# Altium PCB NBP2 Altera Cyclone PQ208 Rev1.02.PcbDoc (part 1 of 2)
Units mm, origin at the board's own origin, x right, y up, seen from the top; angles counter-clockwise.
Board outline 69 x 80.99 mm, 2 copper layers (Top Layer, Bottom Layer); 52 components, 189 nets, 558 pads, 192 vias.
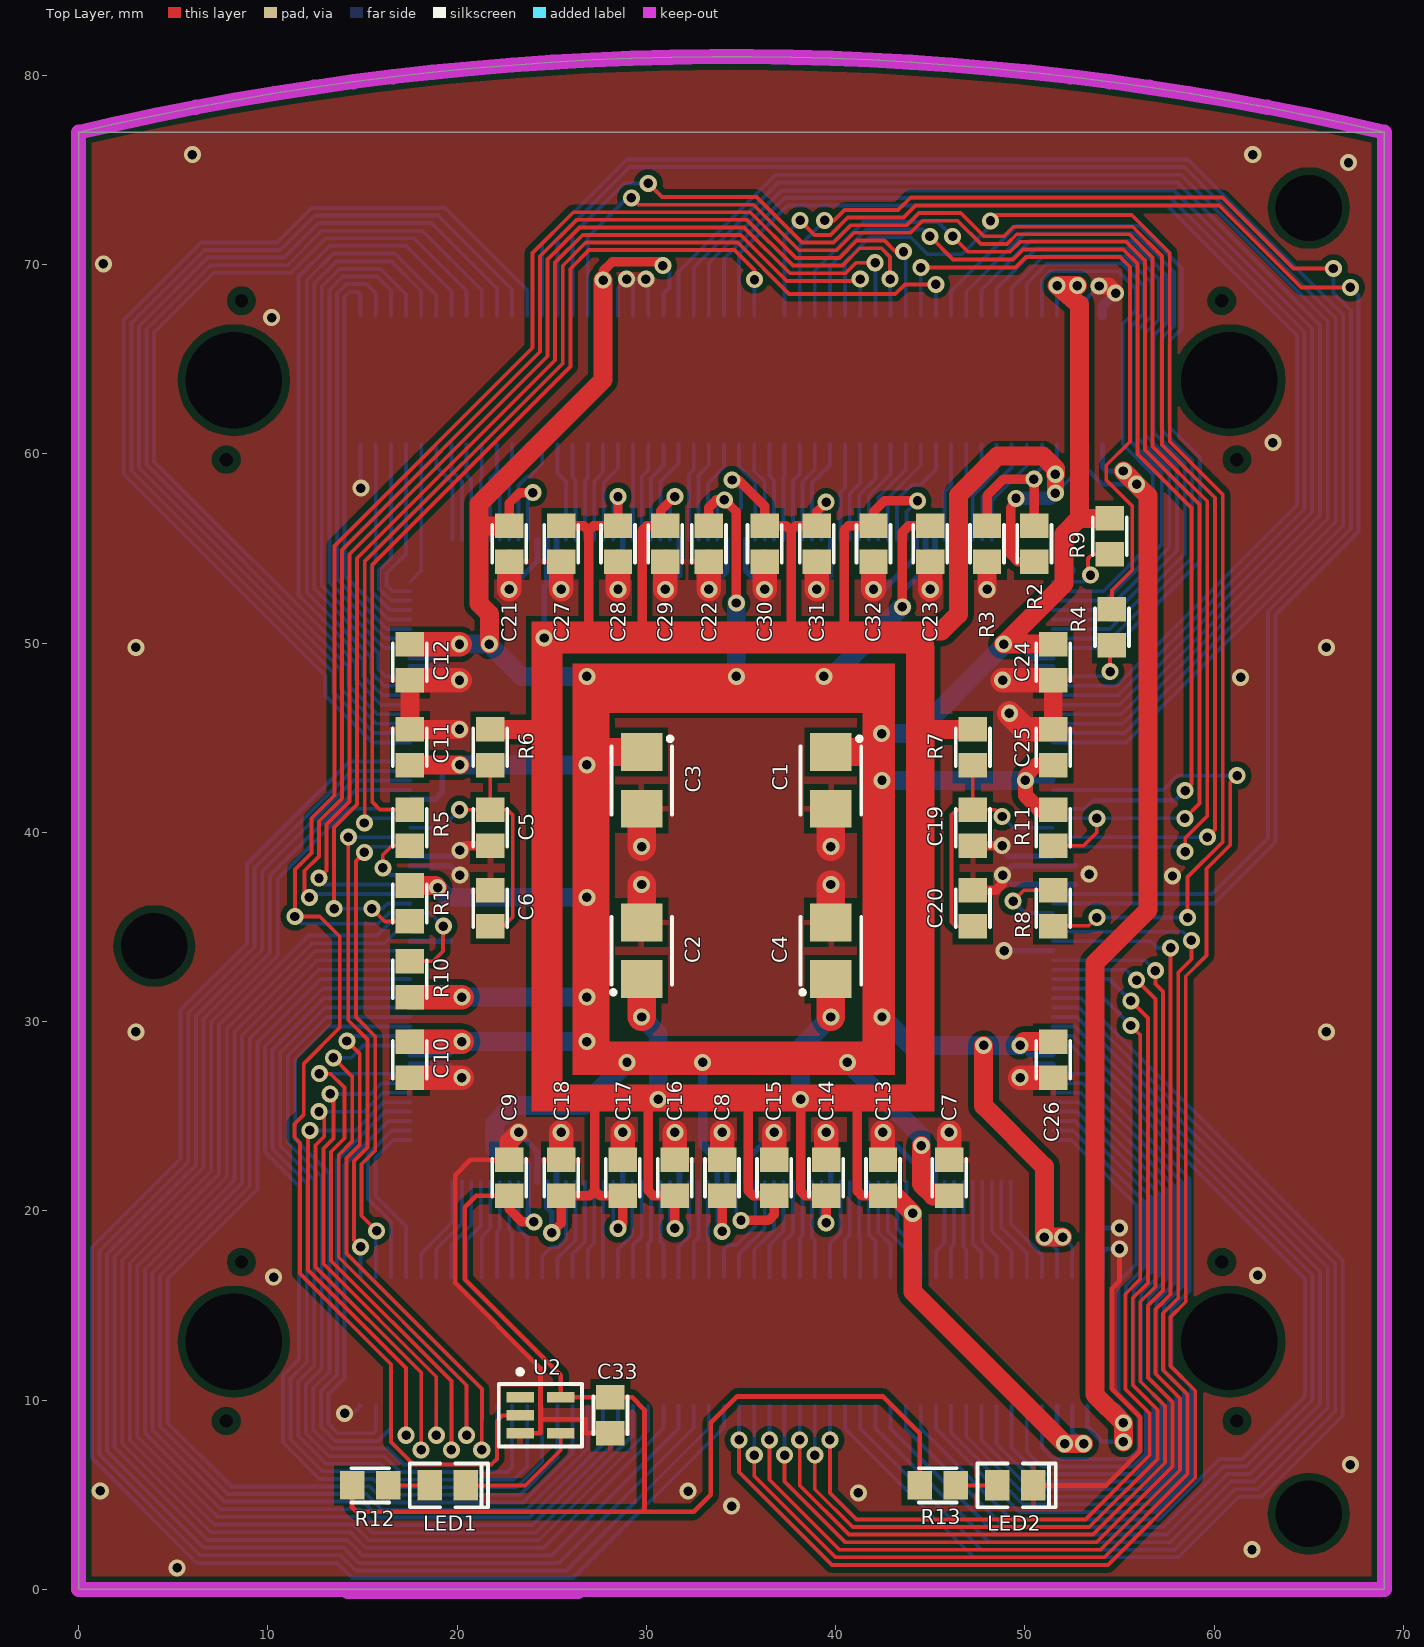
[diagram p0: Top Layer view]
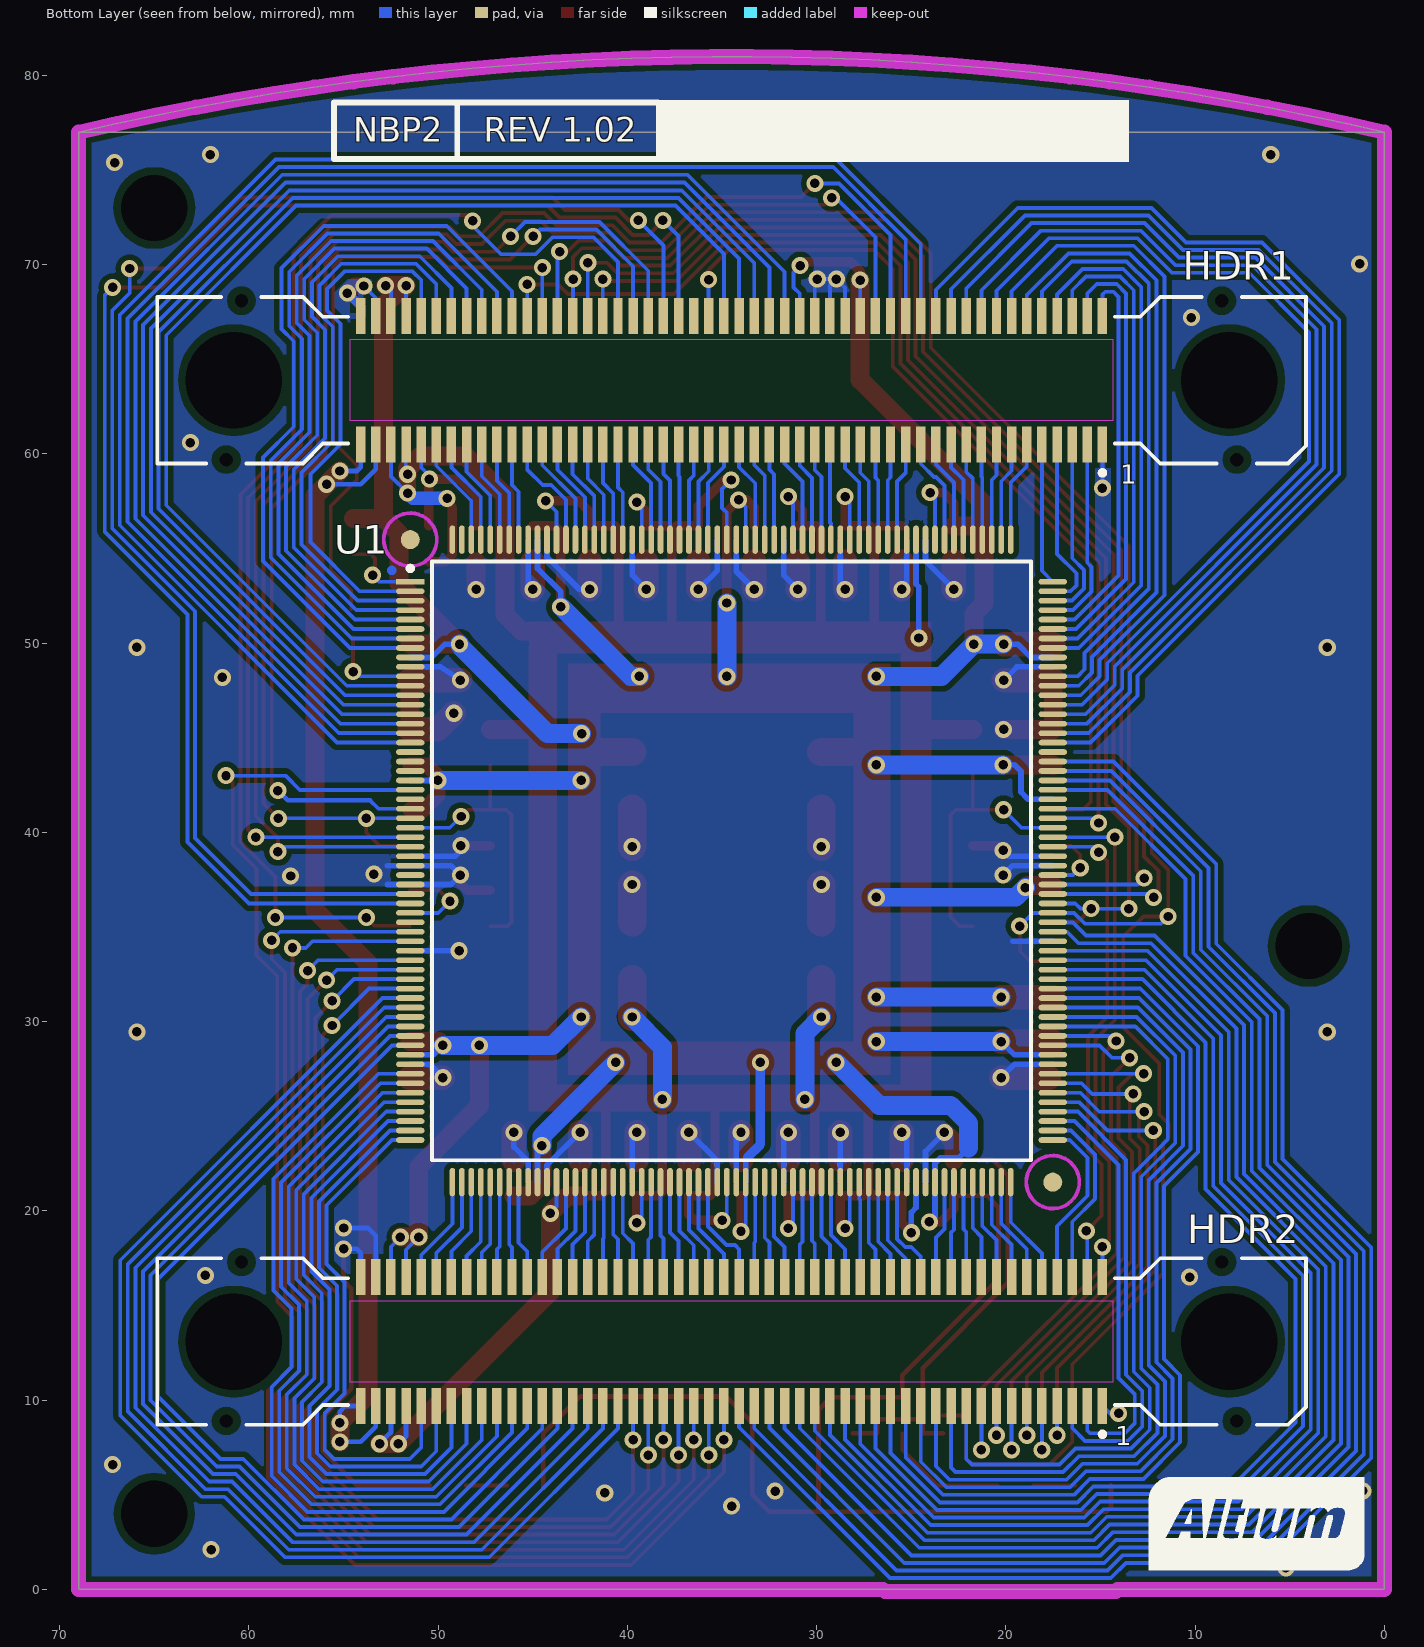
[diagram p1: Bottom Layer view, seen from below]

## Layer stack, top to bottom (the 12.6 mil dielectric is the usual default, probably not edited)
Top Layer: signal copper 0.0356
Dielectric: core 0.32, FR-4, Dk 4.8
Bottom Layer: signal copper 0.0356

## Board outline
0,0 0,77 ccw(c0.001,77) 0.001,77 cw(c34.5,-69.801) 0.001,77 69,77 69,0

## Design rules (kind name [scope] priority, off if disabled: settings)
Clearance Clearance_Unplated_Pads [PadIsPlated = 'False'] p1: gap=0.4 // Slightly larger clearance around unplated holes
Clearance Clearance_Polygons [InPolygon] p2: gap=0.3
Clearance [All] p3: gap=0.2
ComponentClearance [All] p1: gap=0.2 collisioncheckmode=3 verticalgap=0.254 showdistances=FALSE
FabricationTestPointUsage TestPointUsage [All] p1 off: valid=0 allowmultiple=FALSE
FabricationTestpoint Testpoint [All] p1 off: side=3 testpointundercomponent=TRUE minsize=1.016 maxsize=2.54 preferedsize=1.524 minholesize=0 maxholesize=1.016 preferedholesize=0.813 testpointgrid=0.025 allowsidetop=TRUE allowsidebottom=TRUE usegrid=TRUE gridtolerance=0
HoleSize [All] p1: absolutevalues=TRUE maxlimit=5.2 minlimit=0.4 maxpercent=80.000 minpercent=20.000
PlaneClearance [All] p1: clearance=0.5
PlaneConnect [All] p1: planeconnectstyle=Relief reliefexpansion=0.5 reliefentries=4 reliefconductorwidth=0.25 reliefairgap=0.25
PolygonConnect PolygonConnect_Satellite_ID_Pads [InPadClass('Satellite ID Pads')] p1: connectstyle=NoConnect reliefconductorwidth=0.254 reliefentries=4 polygonreliefangle="90 Angle"
PolygonConnect [All] p2: connectstyle=Relief reliefconductorwidth=0.3 reliefentries=4 polygonreliefangle="90 Angle"
RoomDefinition BOCD_CycloneEPC12 [InComponentClass('BOCD_CycloneEPC12')] p1 off: confinementstyle=ConfineIn formatcopy=TRUE lockcomponents=FALSE outline 0,0 69,0 69,77 0,77
RoutingVias [All] p1: holewidth=0.5 width=0.9 viastyle="Through Hole" minholewidth=0.5 minwidth=0.9 maxholewidth=0.5 maxwidth=0.9
SMDNeckDown [All] p1: percent=100.000
SilkscreenOverComponentPads [All] p1: minsilkscreentomaskgap=0.254
SolderMaskExpansion SolderMaskExpansion_Vias [Isvia] p1: expansion=-0.46
SolderMaskExpansion [All] p2: expansion=0.1
Width Width_Power_Nets [InNetClass('Power Nets')] p1: maxlimit=2.5 minlimit=0.15 preferedwidth=0.25 toplayer_prefwidth=0.15
Width [All] p2: maxlimit=1.5 minlimit=0.2 preferedwidth=0.2
21 further rules are at their usual default settings.

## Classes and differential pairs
pad class "Satellite ID Pads": HDR1-36 HDR1-38 HDR1-40
net class "Power Nets": 5V GND VCC VCCINT

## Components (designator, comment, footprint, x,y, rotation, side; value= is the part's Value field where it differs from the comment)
C1 "10uF" MCCT-B 39.75,42.75 r270 top
C2 "10uF" MCCT-B 29.75,33.75 r90 top
C3 "10uF" MCCT-B 29.75,42.75 r270 top
C4 "10uF" MCCT-B 39.75,33.75 r90 top
C5 "0.1uF" CC2012-0805 21.75,40.25 r270 top
C6 "0.001uF" CC2012-0805 21.75,36 r90 top
C7 "0.1uF" CC2012-0805 46,21.75 r90 top
C8 "0.1uF" CC2012-0805 34,21.75 r90 top
C9 "0.1uF" CC2012-0805 22.75,21.75 r90 top
C10 "0.1uF" CC2012-0805 17.5,28 r270 top
C11 "0.1uF" CC2012-0805 17.5,44.5 r90 top
C12 "0.1uF" CC2012-0805 17.5,49 r270 top
C13 "0.1uF" CC2012-0805 42.5,21.75 r90 top
C14 "0.1uF" CC2012-0805 39.5,21.75 r90 top
C15 "0.1uF" CC2012-0805 36.75,21.75 r90 top
C16 "0.1uF" CC2012-0805 31.5,21.75 r90 top
C17 "0.1uF" CC2012-0805 28.75,21.75 r90 top
C18 "0.1uF" CC2012-0805 25.5,21.75 r90 top
C19 "0.1uF" CC2012-0805 47.25,40.25 r90 top
C20 "0.001uF" CC2012-0805 47.25,36 r270 top
C21 "0.1uF" CC2012-0805 22.75,55.25 r90 top
C22 "0.1uF" CC2012-0805 33.3,55.25 r90 top
C23 "0.1uF" CC2012-0805 45,55.25 r90 top
C24 "0.1uF" CC2012-0805 51.5,49 r90 top
C25 "0.1uF" CC2012-0805 51.5,44.5 r270 top
C26 "0.1uF" CC2012-0805 51.5,28 r90 top
C27 "0.1uF" CC2012-0805 25.5,55.25 r90 top
C28 "0.1uF" CC2012-0805 28.5,55.25 r90 top
C29 "0.1uF" CC2012-0805 31,55.25 r90 top
C30 "0.1uF" CC2012-0805 36.25,55.25 r90 top
C31 "0.1uF" CC2012-0805 39,55.25 r90 top
C32 "0.1uF" CC2012-0805 42,55.25 r90 top
C33 "0.1uF" CC2012-0805 28.1,9.2 r270 top
HDR1 "54075-1009" 54075 34.5,63.9 r0 bottom locked
HDR2 "54075-1009" 54075 34.5,13.1 r0 bottom locked
LED1 "HSMG-C170" "SMD _LED" 19.5,5.5 r180 top locked
LED2 "HSMH-C170" "SMD _LED" 49.5,5.5 r180 top locked
R1 "4K7" CC2012-0805 17.5,36.25 r270 top
R2 "DO NOT INSTALL" CC2012-0805 50.5,55.25 r90 top
R3 "47R" CC2012-0805 48,55.25 r270 top
R4 "100R" CC2012-0805 54.6,50.85 r90 top
R5 "100R" CC2012-0805 17.5,40.25 r270 top
R6 "1R" CC2012-0805 21.75,44.5 r270 top
R7 "1R" CC2012-0805 47.25,44.5 r270 top
R8 "33R" CC2012-0805 51.5,36 r270 top
R9 "4K7" CC2012-0805 54.483,55.651 r270 top
R10 "4K7" CC2012-0805 17.5,32.25 r90 top
R11 "4K7" CC2012-0805 51.5,40.25 r270 top
R12 "270R" CC2012-0805 15.4,5.5 r0 top
R13 "270R" CC2012-0805 45.4,5.5 r0 top
U1 "Cyclone EP1C12Q240C8" F-QFP32X32-G240/P.5N(RS) 34.5,38.5 r180 bottom locked
U2 "SN74LVC1G04DBV" SO-G5/P.95 24.4,9.2 r270 top

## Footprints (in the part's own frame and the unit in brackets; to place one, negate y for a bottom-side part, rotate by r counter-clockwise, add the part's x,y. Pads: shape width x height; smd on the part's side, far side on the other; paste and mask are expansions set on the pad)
54075 [mm] "Connector; Docking Station, Receptacle; 100 Position; Vertical"
  rect 0.5x1.9 smd: 1(-19.6,3.4) 2(-19.6,-3.4) 3(-18.8,3.4) 4(-18.8,-3.4) 5(-18,3.4) 6(-18,-3.4) 7(-17.2,3.4) 8(-17.2,-3.4) 9(-16.4,3.4) 10(-16.4,-3.4) 11(-15.6,3.4) 12(-15.6,-3.4) 13(-14.8,3.4) 14(-14.8,-3.4) 15(-14,3.4) 16(-14,-3.4) 17(-13.2,3.4) 18(-13.2,-3.4) 19(-12.4,3.4) 20(-12.4,-3.4) 21(-11.6,3.4) 22(-11.6,-3.4) 23(-10.8,3.4) 24(-10.8,-3.4) 25(-10,3.4) 26(-10,-3.4) 27(-9.2,3.4) 28(-9.2,-3.4) 29(-8.4,3.4) 30(-8.4,-3.4) 31(-7.6,3.4) 32(-7.6,-3.4) 33(-6.8,3.4) 34(-6.8,-3.4) 35(-6,3.4) 36(-6,-3.4) 37(-5.2,3.4) 38(-5.2,-3.4) 39(-4.4,3.4) 40(-4.4,-3.4) 41(-3.6,3.4) 42(-3.6,-3.4) 43(-2.8,3.4) 44(-2.8,-3.4) 45(-2,3.4) 46(-2,-3.4) 47(-1.2,3.4) 48(-1.2,-3.4) 49(-0.4,3.4) 50(-0.4,-3.4) 51(0.4,3.4) 52(0.4,-3.4) 53(1.2,3.4) 54(1.2,-3.4) 55(2,3.4) 56(2,-3.4) 57(2.8,3.4) 58(2.8,-3.4) 59(3.6,3.4) 60(3.6,-3.4) 61(4.4,3.4) 62(4.4,-3.4) 63(5.2,3.4) 64(5.2,-3.4) 65(6,3.4) 66(6,-3.4) 67(6.8,3.4) 68(6.8,-3.4) 69(7.6,3.4) 70(7.6,-3.4) 71(8.4,3.4) 72(8.4,-3.4) 73(9.2,3.4) 74(9.2,-3.4) 75(10,3.4) 76(10,-3.4) 77(10.8,3.4) 78(10.8,-3.4) 79(11.6,3.4) 80(11.6,-3.4) 81(12.4,3.4) 82(12.4,-3.4) 83(13.2,3.4) 84(13.2,-3.4) 85(14,3.4) 86(14,-3.4) 87(14.8,3.4) 88(14.8,-3.4) 89(15.6,3.4) 90(15.6,-3.4) 91(16.4,3.4) 92(16.4,-3.4) 93(17.2,3.4) 94(17.2,-3.4) 95(18,3.4) 96(18,-3.4) 97(18.8,3.4) 98(18.8,-3.4) 99(19.6,3.4) 100(19.6,-3.4)
  round 0.5 hole 0.7 unplated: MH1(-26.7,4.2) MH2(-25.9,-4.2) MH3(26.7,4.2) MH4(25.9,-4.2)
  round 4.8 hole 5.1 unplated: MH5(-26.3,0) MH6(26.3,0)
  Top Layer keep-out region: -20.15,2.15 20.15,2.15 20.15,-2.15 -20.15,-2.15
  silkscreen extent -30.35,-4.4 30.35,5.02
CC2012-0805 [mm]
  rect 1.3x1.5 smd: 1(-0.95,0) 2(0.95,0)
  silkscreen extent -1,-0.9 1,0.9
F-QFP32X32-G240/P.5N(RS) [mm]
  rect 1.5x0.3 smd: 1(-16.975,14.75)
  oval 1.5x0.3 smd: 2(-16.975,14.25) 3(-16.975,13.75) 4(-16.975,13.25) 5(-16.975,12.75) 6(-16.975,12.25) 7(-16.975,11.75) 8(-16.975,11.25) 9(-16.975,10.75) 10(-16.975,10.25) 11(-16.975,9.75) 12(-16.975,9.25) 13(-16.975,8.75) 14(-16.975,8.25) 15(-16.975,7.75) 16(-16.975,7.25) 17(-16.975,6.75) 18(-16.975,6.25) 19(-16.975,5.75) 20(-16.975,5.25) 21(-16.975,4.75) 22(-16.975,4.25) 23(-16.975,3.75) 24(-16.975,3.25) 25(-16.975,2.75) 26(-16.975,2.25) 27(-16.975,1.75) 28(-16.975,1.25) 29(-16.975,0.75) 30(-16.975,0.25) 31(-16.975,-0.25) 32(-16.975,-0.75) 33(-16.975,-1.25) 34(-16.975,-1.75) 35(-16.975,-2.25) 36(-16.975,-2.75) 37(-16.975,-3.25) 38(-16.975,-3.75) 39(-16.975,-4.25) 40(-16.975,-4.75) 41(-16.975,-5.25) 42(-16.975,-5.75) 43(-16.975,-6.25) 44(-16.975,-6.75) 45(-16.975,-7.25) 46(-16.975,-7.75) 47(-16.975,-8.25) 48(-16.975,-8.75) 49(-16.975,-9.25) 50(-16.975,-9.75) 51(-16.975,-10.25) 52(-16.975,-10.75) 53(-16.975,-11.25) 54(-16.975,-11.75) 55(-16.975,-12.25) 56(-16.975,-12.75) 57(-16.975,-13.25) 58(-16.975,-13.75) 59(-16.975,-14.25) 60(-16.975,-14.75) 121(16.975,-14.75) 122(16.975,-14.25) 123(16.975,-13.75) 124(16.975,-13.25) 125(16.975,-12.75) 126(16.975,-12.25) 127(16.975,-11.75) 128(16.975,-11.25) 129(16.975,-10.75) 130(16.975,-10.25) 131(16.975,-9.75) 132(16.975,-9.25) 133(16.975,-8.75) 134(16.975,-8.25) 135(16.975,-7.75) 136(16.975,-7.25) 137(16.975,-6.75) 138(16.975,-6.25) 139(16.975,-5.75) 140(16.975,-5.25) 141(16.975,-4.75) 142(16.975,-4.25) 143(16.975,-3.75) 144(16.975,-3.25) 145(16.975,-2.75) 146(16.975,-2.25) 147(16.975,-1.75) 148(16.975,-1.25) 149(16.975,-0.75) 150(16.975,-0.25) 151(16.975,0.25) 152(16.975,0.75) 153(16.975,1.25) 154(16.975,1.75) 155(16.975,2.25) 156(16.975,2.75) 157(16.975,3.25) 158(16.975,3.75) 159(16.975,4.25) 160(16.975,4.75) 161(16.975,5.25) 162(16.975,5.75) 163(16.975,6.25) 164(16.975,6.75) 165(16.975,7.25) 166(16.975,7.75) 167(16.975,8.25) 168(16.975,8.75) 169(16.975,9.25) 170(16.975,9.75) 171(16.975,10.25) 172(16.975,10.75) 173(16.975,11.25) 174(16.975,11.75) 175(16.975,12.25) 176(16.975,12.75) 177(16.975,13.25) 178(16.975,13.75) 179(16.975,14.25) 180(16.975,14.75)
  oval 0.3x1.5 smd: 61(-14.75,-16.975) 62(-14.25,-16.975) 63(-13.75,-16.975) 64(-13.25,-16.975) 65(-12.75,-16.975) 66(-12.25,-16.975) 67(-11.75,-16.975) 68(-11.25,-16.975) 69(-10.75,-16.975) 70(-10.25,-16.975) 71(-9.75,-16.975) 72(-9.25,-16.975) 73(-8.75,-16.975) 74(-8.25,-16.975) 75(-7.75,-16.975) 76(-7.25,-16.975) 77(-6.75,-16.975) 78(-6.25,-16.975) 79(-5.75,-16.975) 80(-5.25,-16.975) 81(-4.75,-16.975) 82(-4.25,-16.975) 83(-3.75,-16.975) 84(-3.25,-16.975) 85(-2.75,-16.975) 86(-2.25,-16.975) 87(-1.75,-16.975) 88(-1.25,-16.975) 89(-0.75,-16.975) 90(-0.25,-16.975) 91(0.25,-16.975) 92(0.75,-16.975) 93(1.25,-16.975) 94(1.75,-16.975) 95(2.25,-16.975) 96(2.75,-16.975) 97(3.25,-16.975) 98(3.75,-16.975) 99(4.25,-16.975) 100(4.75,-16.975) 101(5.25,-16.975) 102(5.75,-16.975) 103(6.25,-16.975) 104(6.75,-16.975) 105(7.25,-16.975) 106(7.75,-16.975) 107(8.25,-16.975) 108(8.75,-16.975) 109(9.25,-16.975) 110(9.75,-16.975) 111(10.25,-16.975) 112(10.75,-16.975) 113(11.25,-16.975) 114(11.75,-16.975) 115(12.25,-16.975) 116(12.75,-16.975) 117(13.25,-16.975) 118(13.75,-16.975) 119(14.25,-16.975) 120(14.75,-16.975) 181(14.75,16.975) 182(14.25,16.975) 183(13.75,16.975) 184(13.25,16.975) 185(12.75,16.975) 186(12.25,16.975) 187(11.75,16.975) 188(11.25,16.975) 189(10.75,16.975) 190(10.25,16.975) 191(9.75,16.975) 192(9.25,16.975) 193(8.75,16.975) 194(8.25,16.975) 195(7.75,16.975) 196(7.25,16.975) 197(6.75,16.975) 198(6.25,16.975) 199(5.75,16.975) 200(5.25,16.975) 201(4.75,16.975) 202(4.25,16.975) 203(3.75,16.975) 204(3.25,16.975) 205(2.75,16.975) 206(2.25,16.975) 207(1.75,16.975) 208(1.25,16.975) 209(0.75,16.975) 210(0.25,16.975) 211(-0.25,16.975) 212(-0.75,16.975) 213(-1.25,16.975) 214(-1.75,16.975) 215(-2.25,16.975) 216(-2.75,16.975) 217(-3.25,16.975) 218(-3.75,16.975) 219(-4.25,16.975) 220(-4.75,16.975) 221(-5.25,16.975) 222(-5.75,16.975) 223(-6.25,16.975) 224(-6.75,16.975) 225(-7.25,16.975) 226(-7.75,16.975) 227(-8.25,16.975) 228(-8.75,16.975) 229(-9.25,16.975) 230(-9.75,16.975) 231(-10.25,16.975) 232(-10.75,16.975) 233(-11.25,16.975) 234(-11.75,16.975) 235(-12.25,16.975) 236(-12.75,16.975) 237(-13.25,16.975) 238(-13.75,16.975) 239(-14.25,16.975) 240(-14.75,16.975)
  round 1 smd paste-0.51 mask+1: FID1(-16.975,16.975) FID2(16.975,-16.975)
  Top Layer circle w0.25: c-17.951,15.348 r0.125
  Top Layer keep-out circle w0.2: c-16.975,16.975 r1.4
  Top Layer keep-out circle w0.2: c16.975,-16.975 r1.4
  silkscreen extent -17.1,-15.83 15.83,15.83
MCCT-B [mm]
  rect 2x2.2 smd: 1(-1.5,0) 2(1.5,0)
  silkscreen extent -2.3,-1.6 1.8,1.6
"SMD _LED" [mm]
  rect 1.3x1.6 smd: 1(0.95,0) 2(-0.95,0)
  silkscreen extent -2.13,-1.15 2,1.15
SO-G5/P.95 [mm]
  rect 0.55x1.45 smd: 1(-0.95,-1.075) 2(0,-1.075) 3(0.95,-1.075) 4(0.95,1.075) 5(-0.95,1.075)
  silkscreen extent -2.42,-2.2 1.65,2.2

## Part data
C1 C2 C3 C4: library part CAP_POLAR, "Polar Capacitor"
C5 C6 C7 C8 C9 C10 C11 C12 C13 C14 C15 C16 C17 C18 C19 C20 C21 C22 C23 C24 C25 C26 C27 C28 C29 C30 C31 C32 C33: library part CAP, "Capacitor"
HDR1 HDR2: "Board-to-Board, Docking Station, 0.80mm (.031\") Pitch, Shielded Receptacle, Vertical, Ultra Low Profile, SMT"
LED1 LED2: library part HSMX-C670, "Typical RED GaAs SMD LED Agilent make"
R1 R2 R3 R4 R5 R6 R7 R8 R9 R10 R11 R12 R13: library part RES, "Resistor"
U1: library part EP1C12Q240C6_ALT, "Cyclone Family, 1.5V FPGA, 173 I/O Pins, 2 x PLLs, Commercial Grade, Speed Grade 6"
U2: library part SN74AHC1G04DBVR

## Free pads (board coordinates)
  round 3.2 hole 3.5 unplated: LP(4,34) LP(65,4) LP(65,73)

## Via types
v1: diameter 0.9, hole 0.5, Top Layer to Bottom Layer, 192 vias

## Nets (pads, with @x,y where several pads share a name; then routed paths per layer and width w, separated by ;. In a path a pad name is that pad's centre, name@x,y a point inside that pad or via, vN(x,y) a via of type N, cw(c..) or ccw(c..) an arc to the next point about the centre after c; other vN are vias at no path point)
5V: HDR1.97 HDR1.99 HDR2.97 HDR2.99 | length 65.4
  Top Layer w1: v1(55.2,7.8) v1(55.2,8.8) 53.7,10.3 53.7,33.1 56.5,35.9 56.5,57.8 v1(55.2,59.1)
  Bottom Layer w0.25: HDR2.97@53.3,9.7 53.3,8.6 54.1,7.8 v1(55.2,7.8) ; HDR1.97@53.3,60.5 53.3,59.2 54.1,58.4 v1(55.9,58.4) ; HDR2.99@54.1,9.7 54.9,9.7 55.2,9.4 v1(55.2,8.8) ; HDR1.99@54.1,60.5 54.1,59.3 54.3,59.1 v1(55.2,59.1)
AUDIO_SPI_CSN: HDR1.11 U1.181 | length 5.4
  Bottom Layer w0.2: HDR1.11@18.9,60.5 18.9,59.346 19.75,58.496 U1.181@19.75,55.475
BLUE0: HDR1.14 U1.168 | length 36.5
  Bottom Layer w0.2: U1.168@17.525,47.25 16.05,47.25 15.05,48.25 15.05,49.109 11.625,52.534 11.625,69.375 13.25,71 17.3,71 19.7,68.6 HDR1.14@19.7,67.3
BLUE1: HDR1.16 U1.167 | length 47.2
  Bottom Layer w0.2: U1.167@17.525,46.75 15.975,46.75 14.65,48.075 14.65,48.944 3.988,59.606 3.988,66.422 7.141,69.575 11.225,69.575 13.05,71.4 17.725,71.4 20.5,68.625 HDR1.16@20.5,67.3
BOC_CTS: HDR1.13 U1.182 | length 5.3
  Bottom Layer w0.2: HDR1.13@19.7,60.5 19.7,59.112 20.25,58.561 U1.182@20.25,55.475
BOC_RTS: HDR1.17 U1.184 | length 5
  Bottom Layer w0.2: U1.184@21.25,55.475 21.25,58.751 21.3,58.801 HDR1.17@21.3,60.5
BOC_RX: HDR1.19 U1.185 | length 5.2
  Bottom Layer w0.2: U1.185@21.75,55.475 21.75,58.705 22.1,59.055 HDR1.19@22.1,60.5
BOC_TX: HDR1.15 U1.183 | length 5.1
  Bottom Layer w0.2: HDR1.15@20.5,60.5 20.5,58.877 20.75,58.627 U1.183@20.75,55.475
BUZZER: HDR2.24 U1.113 | length 5.2
  Bottom Layer w0.2: U1.113@23.25,21.525 23.25,19.05 23.7,18.6 HDR2.24@23.7,16.5
CAN_RXD: HDR1.4 U1.175 | length 23.7
  Bottom Layer w0.2: HDR1.4@15.7,67.3 15.7,68.475 15.2,68.975 14.15,68.975 13.65,68.475 13.65,53.4 16.3,50.75 U1.175@17.525,50.75
CAN_TXD: HDR1.2 U1.176 | length 21.3
  Bottom Layer w0.2: HDR1.2@14.9,67.3 14.9,68.425 14.75,68.575 14.325,68.575 14.05,68.3 14.05,53.575 16.375,51.25 U1.176@17.525,51.25
FPGA_AUX0: HDR1.86 U1.5 | length 35
  Bottom Layer w0.2: HDR1.86@48.5,67.3 48.5,68.75 50.6,70.85 55.475,70.85 57.075,69.25 57.075,67.092 56.388,66.405 56.388,60.99 58.039,59.339 58.039,54.889 54.4,51.25 U1.5@51.475,51.25
FPGA_AUX1: HDR1.88 U1.4 | length 32.6
  Bottom Layer w0.2: HDR1.88@49.3,67.3 49.3,68.775 50.975,70.45 55.3,70.45 56.675,69.075 56.675,67.258 55.982,66.565 55.982,60.831 57.633,59.18 57.633,55.052 54.331,51.75 U1.4@51.475,51.75
FPGA_AUX2: HDR1.90 U1.3 | length 30.4
  Bottom Layer w0.2: HDR1.90@50.1,67.3 50.1,68.975 51.175,70.05 55.125,70.05 56.275,68.9 56.275,67.424 55.575,66.724 55.575,60.672 57.226,59.021 57.226,55.22 54.257,52.25 U1.3@51.475,52.25
FPGA_AUX3: HDR1.92 U1.2 | length 28.1
  Bottom Layer w0.2: HDR1.92@50.9,67.3 50.9,69.2 51.35,69.65 54.95,69.65 55.875,68.725 55.875,67.589 55.169,66.883 55.169,60.512 56.751,58.93 56.751,55.348 54.153,52.75 U1.2@51.475,52.75
FPGA_CCLK: HDR1.66 R8.2 | length 67.1
  Top Layer w0.2: v1(48.184,72.314) 48.497,72.627 55.643,72.627 57.65,70.62 57.65,60.655 60.452,57.853 60.452,39.497 58.6,37.645 v1(58.6,35.5) ; R8.2@51.5,35.05 51.525,35.075 53.375,35.075 v1(53.8,35.5)
  Bottom Layer w0.2: HDR1.66@40.5,67.3 40.5,70.153 41.797,71.451 43.967,71.451 44.861,70.557 46.685,70.557 48.184,72.056 v1(48.184,72.314) ; v1(53.8,35.5) v1(58.6,35.5)
FPGA_CCLK#: R8.1 U1.36 | length 4.7
  Top Layer w0.2: v1(49.378,36.373) 49.955,36.95 R8.1@51.5,36.95
  Bottom Layer w0.2: v1(49.378,36.373) 50,35.75 U1.36@51.475,35.75
FPGA_CLK: HDR2.2 U1.153 | length 27.4
  Top Layer w0.2: v1(14.25,39.75) 14.25,30.08 15.265,29.064 15.265,23.354 14.548,22.637 14.548,18.452 v1(14.9,18.1)
  Bottom Layer w0.2: v1(14.25,39.75) U1.153@17.525,39.75 ; HDR2.2@14.9,16.5 v1(14.9,18.1)
FPGA_CLK_1: HDR1.30 U1.28 | length 80
  Top Layer w0.2: v1(30.099,74.295) 30.823,73.571 35.818,73.571 38.218,71.171 39.885,71.171 40.805,72.091 43.77,72.091 44.406,72.727 46.609,72.727 47.835,71.501 48.895,71.501 49.403,72.009 55.695,72.009 57.25,70.454 57.25,60.479 60.046,57.683 60.046,40.157 v1(59.639,39.751)
  Bottom Layer w0.2: HDR1.30@26.1,67.3 26.1,71.569 28.244,73.712 28.826,74.295 v1(30.099,74.295) ; U1.28@51.475,39.75 v1(59.639,39.751) v1(59.639,39.751)
FPGA_CLK_2: HDR1.32 U1.29 | length 78.1
  Top Layer w0.2: v1(29.21,73.533) 29.572,73.171 35.652,73.171 38.058,70.764 40.044,70.764 40.971,71.691 43.954,71.691 44.59,72.327 46.444,72.327 47.681,71.09 49.05,71.09 49.569,71.609 55.53,71.609 56.75,70.389 56.75,60.395 59.639,57.506 59.639,40.869 58.471,39.7 v1(58.471,38.989)
  Bottom Layer w0.2: HDR1.32@26.9,67.3 26.9,71.45 28.983,73.533 v1(29.21,73.533) ; U1.29@51.475,39.25 58.21,39.25 v1(58.471,38.989)
FPGA_DIN: HDR1.64 U1.25 | length 57.4
  Top Layer w0.2: v1(44.983,71.501) 46.203,70.282 49.373,70.282 49.9,70.809 55.198,70.809 55.95,70.057 55.95,60.001 58.801,57.15 58.801,42.545 v1(58.471,42.215)
  Bottom Layer w0.2: HDR1.64@39.7,67.3 39.7,69.919 41.639,71.858 44.627,71.858 v1(44.983,71.501) ; U1.25@51.475,41.25 53.15,41.25 53.598,41.698
  Bottom Layer w0.23: 53.598,41.698 57.954,41.698 v1(58.471,42.215)
FPGA_DONE: HDR1.74 R10.2 U1.145 U2.2 | length 119.8
  Top Layer w0.2: R10.2@17.5,33.2 18.725,33.2 19.25,33.725 19.25,35.025 v1(19.275,35.05) ; U2.2@23.325,9.2 22.4,9.2 22.1,8.9 22.1,6.9 21.8,6.6 17.7,6.6 16.5,7.8 16.5,11.9 11.7,16.7 11.7,23.6 11.4,23.9 11.4,24.6 11.9,25.1 11.9,27.8 13.8,29.7 13.8,34.5 12.74,35.56 v1(11.43,35.56) 11.43,38.049 12.3,38.919 12.3,40.756 13.513,41.969 13.513,55.144 23.978,65.608 23.978,70.612 26.137,72.771 35.486,72.771 37.899,70.358 40.203,70.358 41.118,71.272 42.577,71.272 43.161,70.688 v1(43.586,70.688)
  Bottom Layer w0.2: v1(11.43,35.56) 11.811,35.179 15.829,35.179 16.4,35.75 18.575,35.75 v1(19.275,35.05) ; v1(43.586,70.688) 43.7,70.548 HDR1.74@43.7,67.3
FPGA_INIT: HDR1.68 R1.2 U1.146 | length 65.2
  Top Layer w0.2: v1@13.487,35.966 v1@13.487,35.975 ; v1(13.5,35.975) 13.5,40.259 14.713,41.472 14.713,54.489 25.178,64.954 25.178,70.115 26.634,71.571 34.989,71.571 37.421,69.139 41.199,69.139 v1(41.3,69.24) ; v1(15.5,35.975) 16.175,35.3 R1.2@17.5,35.3
  Bottom Layer w0.2: v1@13.496,35.975 16.059,35.975 16.334,36.25 U1.146@17.525,36.25 U1.146@17.5,36.225 ; v1@15.491,35.966 v1(15.5,35.975) ; HDR1.68@41.3,67.3 v1(41.3,69.24)
FPGA_M0: HDR1.60 U1.34 | length 79.4
  Top Layer w0.2: v1(39.421,72.339) 39.922,72.339 40.474,72.891 43.3,72.891 43.967,73.558 60.442,73.558 64.2,69.8 v1(66.3,69.8)
  Bottom Layer w0.2: HDR1.60@38.1,67.3 38.1,71.018 v1(39.421,72.339) ; U1.34@51.475,36.75 59.889,36.75 62.846,39.707 62.846,51.689 67.225,56.068 67.225,67.575 66.3,68.5 v1(66.3,69.8)
FPGA_M1: HDR1.58 U1.35 | length 81.6
  Top Layer w0.2: v1(38.125,72.339) 38.887,71.577 39.726,71.577 40.639,72.491 43.586,72.491 44.221,73.127 60.273,73.127 64.6,68.8 v1(67.2,68.8)
  Bottom Layer w0.2: HDR1.58@37.3,67.3 37.3,71.514 v1(38.125,72.339) ; U1.35@51.475,36.25 59.999,36.25 63.246,39.497 63.246,51.523 67.625,55.902 67.625,68.375 v1(67.2,68.8)
FPGA_PROGRAM: HDR1.62 R11.2 U1.26 | length 63.5
  Top Layer w0.2: v1(46.177,71.501) 46.99,70.688 49.214,70.688 49.734,71.209 55.364,71.209 56.35,70.223 56.35,60.211 59.233,57.328 59.233,41.533 v1(58.45,40.75) ; R11.2@51.5,39.3 53.1,39.3 53.8,40 v1(53.8,40.75)
  Bottom Layer w0.2: HDR1.62@38.9,67.3 38.9,69.685 41.478,72.263 45.415,72.263 v1(46.177,71.501) ; U1.26@51.475,40.75 v1(53.8,40.75) v1(58.45,40.75)
FPGA_TCK: HDR1.72 U1.147 | length 68.6
  Top Layer w0.2: v1(12.192,36.576) 11.938,36.83 11.938,37.973 12.7,38.735 12.7,40.59 13.913,41.803 13.913,54.934 24.378,65.399 24.378,70.447 26.302,72.371 35.32,72.371 37.74,69.952 40.363,69.952 41.277,70.866 42.418,70.866 42.875,70.409 v1(42.875,69.24)
  Bottom Layer w0.2: v1(12.192,36.576) v1@12.366,36.75 ; v1@12.239,36.75 U1.147@17.525,36.75 ; v1(42.875,69.24) HDR1.72@42.9,67.3
FPGA_TDI: HDR1.78 U1.155 | length 59.5
  Top Layer w0.2: v1(15.1,40.5) 15.113,40.513 15.113,54.312 25.578,64.777 25.578,69.949 26.799,71.171 34.823,71.171 37.541,68.453 43.155,68.453 43.663,68.961 v1(45.3,68.961)
  Bottom Layer w0.2: v1(15.1,40.5) 15.35,40.75 U1.155@17.525,40.75 ; HDR1.78@45.3,67.3 v1(45.3,68.961)
FPGA_TDO: HDR1.54 R5.1 | length 47.7
  Top Layer w0.2: R5.1@17.5,41.2 15.925,41.2 15.519,41.605 15.519,54.153 25.984,64.618 25.984,69.79 26.965,70.771 34.658,70.771 35.712,69.716 v1(35.712,69.215)
  Bottom Layer w0.2: HDR1.54@35.7,67.3 v1(35.712,69.215)
FPGA_TDO#: R5.2 U1.149 | length 3.9
  Top Layer w0.2: v1(16.075,38.125) 16.075,38.825 16.55,39.3 R5.2@17.5,39.3
  Bottom Layer w0.2: v1(16.075,38.125) 16.45,37.75 U1.149@17.525,37.75
FPGA_TMS: HDR1.70 U1.148 | length 64.7
  Top Layer w0.2: v1(12.7,37.592) 13.1,37.992 13.1,40.425 14.313,41.638 14.313,54.699 24.778,65.164 24.778,70.281 26.468,71.971 35.155,71.971 37.581,69.545 40.522,69.545 41.081,70.104 v1(42.088,70.104)
  Bottom Layer w0.2: v1(12.7,37.592) 13.042,37.25 U1.148@17.525,37.25 ; v1(42.088,70.104) 42.1,70.092 HDR1.70@42.1,67.3
GND: C1.2 C2.2 C3.2 C4.2 C5.2 C6.2 C7.2 C8.2 C9.2 C10.2 C11.2 C12.2 C13.2 C14.2 C15.2 C16.2 C17.2 C18.2 C19.1 C20.1 C21.1 C22.1 C23.1 C24.1 C25.1 C26.1 C27.1 C28.1 C29.1 C30.1 C31.1 C32.1 C33.2 HDR1.1 HDR1.36 HDR1.38 HDR1.40 HDR1.98 HDR1.100 HDR2.1 HDR2.98 HDR2.100 LED2.2 R3.2 U1.10 U1.30 U1.31 U1.33 U1.40 U1.52 U1.69 U1.71 U1.80 U1.89 U1.91 U1.96 U1.102 U1.109 U1.111 U1.129 U1.142 U1.150 U1.151 U1.171 U1.190 U1.192 U1.199 U1.205 U1.210 U1.212 U1.221 U1.230 U1.232 U2.3 | length 210.3
  Top Layer w0.25: C9.2@22.75,22.7 20.7,22.7 19.9,21.9 19.9,16.2 24.4,11.7 24.4,8.25 U2.3@23.325,8.25 ; 24.4,9 26.8,9 26.8,8.25 C33.2@28.1,8.25 ; LED2.2@50.45,5.5 54.3,5.5 56.1,7.3 56.1,9.1 54.6,10.6 54.6,15.9 55,16.3 v1(55,18)
  Top Layer w0.5: v1(20.15,39.05) 20.4,39.3 C5.2@21.75,39.3 ; C20.1@47.25,36.95 48.475,36.95 48.825,37.3 v1(48.825,37.75) ; C19.1@47.25,39.3 v1(48.8,39.3)
  Top Layer w0.9: v1(53.925,68.875) 54.425,68.875 v1(54.8,68.5)
  Top Layer w1: C12.2@17.5,48.05 C11.2@17.5,45.45 v1(20.125,45.45) ; C9.2@22.75,22.7 22.75,23.65 v1(23.25,24.15) ; v1(48,52.85) R3.2@48,54.3 ; C25.1@51.5,45.45 C24.1@51.5,48.05
  Top Layer w1.3: C12.2@17.5,48.05 v1(20.125,48.05) ; C10.2@17.75,27.05 v1(20.25,27.05) ; v1(22.75,52.85) C21.1@22.75,54.3 ; C18.2@25.5,22.7 v1(25.5,24.15) ; v1(25.5,52.85) C27.1@25.5,54.3 ; v1(28.5,52.85) C28.1@28.5,54.3 ; C17.2@28.75,22.7 v1(28.75,24.15) ; v1(31,52.85) C29.1@31,54.3 ; C16.2@31.5,22.7 v1(31.5,24.15) ; v1(33.3,52.85) C22.1@33.3,54.3 ; C8.2@34,22.7 v1(34,24.15) ; v1(36.25,52.85) C30.1@36.25,54.3 ; C15.2@36.75,22.7 v1(36.75,24.15) ; v1(39,52.85) C31.1@39,54.3 ; C14.2@39.5,22.7 v1(39.5,24.15) ; v1(42,52.85) C32.1@42,54.3 ; C13.2@42.5,22.7 v1(42.5,24.15) ; v1(45,52.85) C23.1@45,54.3 ; C7.2@46,22.7 v1(46,24.15) ; v1(48.825,48.05) C24.1@51.5,48.05 ; v1(49.175,46.3) 50.025,45.45 C25.1@51.5,45.45 ; v1(49.75,27.05) C26.1@51.5,27.05
  Top Layer w1.5: C2.2@29.75,35.25 v1(29.75,37.25) ; v1(29.75,39.25) C3.2@29.75,41.25 ; C4.2@39.75,35.25 v1(39.75,37.25) ; v1(39.75,39.25) C1.2@39.75,41.25
  Bottom Layer w0.2: v1(14.05,9.3) 14.5,9.3 HDR2.1@14.9,9.7 HDR2.1@14.825,9.775 ; HDR1.1@14.9,60.5 14.9,58.45 v1(14.91,58.191) ; U1.150@17.525,38.25 U1.150@17.55,38.275 ; HDR1.36@28.5,67.3 28.5,68.786 v1(28.956,69.242) ; HDR1.38@29.3,67.3 29.3,68.898 v1(28.956,69.242) ; HDR1.40@30.1,67.3 30.1,69.114 v1(29.972,69.242) v1(28.956,69.242) ; HDR1.98@53.3,67.3 53.3,68.25 v1(53.925,68.875)
  Bottom Layer w0.25: HDR2.98@53.3,16.5 53.3,18.7 53.7,19.1 v1(55,19.1) ; HDR2.100@54.1,16.5 54.1,17.8 54.3,18 v1(55,18)
  Bottom Layer w0.3: U1.129@17.525,27.75 19.55,27.75 v1(20.25,27.05) ; U1.142@17.525,34.25 19.625,34.25 ; U1.150@17.525,38.25 19.65,38.25 v1(20.15,37.75) ; U1.151@17.525,38.75 19.85,38.75 v1(20.15,39.05) ; U1.171@17.525,48.75 19.425,48.75 v1(20.125,48.05) ; v1(22.75,52.85) 24.25,54.35 U1.190@24.25,55.475 ; v1(23.25,24.15) 24.25,23.15 U1.111@24.25,21.525 ; U1.109@25.25,21.525 25.25,23.9 v1(25.5,24.15) ; U1.192@25.25,55.475 25.25,53.1 v1(25.5,52.85) ; v1(28.5,52.85) 28.75,53.1 U1.199@28.75,55.475 ; U1.102@28.75,21.525 v1(28.75,24.15) ; v1(31,52.85) 31.75,53.6 U1.205@31.75,55.475 ; v1(31.5,24.15) 31.75,23.9 U1.96@31.75,21.525 ; v1(33.3,52.85) 34.25,53.8 U1.210@34.25,55.475 ; v1(34,24.15) 34.25,23.9 U1.91@34.25,21.525 ; U1.89@35.25,21.525 35.25,22.65 v1(36.75,24.15) ; U1.212@35.25,55.475 35.25,53.85 v1(36.25,52.85) ; v1(39,52.85) 39.75,53.6 U1.221@39.75,55.475 ; v1(39.5,24.15) 39.75,23.9 U1.80@39.75,21.525 ; v1(42,52.85) 42.55,52.85 44.25,54.55 U1.230@44.25,55.475 ; v1(42.5,24.15) 42.525,24.15 44.25,22.425 U1.71@44.25,21.525 ; v1(45,52.85) 45.25,53.1 U1.232@45.25,55.475 ; U1.69@45.25,21.525 45.25,22.625 46,23.375 v1(46,24.15) ; v1(48.8,39.3) 48.8,39.05 49.1,38.75 U1.30@51.475,38.75 ; v1(48.825,48.05) 49.881,48.75 U1.10@51.475,48.75 ; v1(48.9,33.75) U1.40@51.475,33.75 ; v1(49.75,27.05) 50.45,27.75 U1.52@51.475,27.75 ; 52.675,37.25 49.325,37.25 v1(48.825,37.75) 49.325,38.25 52.675,38.25
  Bottom Layer w0.5: HDR1.100@54.1,67.3 54.1,67.825 v1(54.8,68.5)
  other v1: 5.207,1.143 62,2.1 34.5,4.4 41.2,5.1 1.143,5.207 32.2,5.2 67.2,6.6 10.3,16.5 62.3,16.6 3.023,29.464 65.927,29.464 57.8,37.7 53.4,37.8 61.4,48.2 3.023,49.784 65.927,49.784 63.1,60.6 10.2,67.2 1.309,70.04 67.1,75.4 6.008,75.819 62.04,75.819
GREEN0: HDR1.10 U1.170 | length 31.7
  Bottom Layer w0.2: U1.170@17.525,48.25 16.225,48.25 15.85,48.625 15.85,49.484 12.45,52.884 12.45,69 13.625,70.175 16.525,70.175 18.1,68.6 HDR1.10@18.1,67.3
GREEN1: HDR1.12 U1.169 | length 33.9
  Bottom Layer w0.2: U1.169@17.525,47.75 16.15,47.75 15.45,48.45 15.45,49.275 12.05,52.675 12.05,69.175 13.475,70.6 16.7,70.6 18.9,68.4 HDR1.12@18.9,67.3
HDRIVE: HDR1.18 U1.166 | length 49.6
  Bottom Layer w0.2: U1.166@17.525,46.25 15.8,46.25 14.25,47.8 14.25,48.778 3.588,59.44 3.588,66.588 6.975,69.975 11.05,69.975 12.875,71.8 18.15,71.8 21.3,68.65 HDR1.18@21.3,67.3
INIT_DONE: R9.2 U1.1 | length 4.3
  Top Layer w0.2: v1(53.467,53.594) 53.34,53.721 53.34,54.483 53.558,54.701 R9.2@54.483,54.701
  Bottom Layer w0.2: U1.1@51.475,53.25 53.123,53.25 v1(53.467,53.594)
IO0: HDR2.7 U1.125 | length 25.8
  Top Layer w0.2: v1(12.217,24.257) 12.116,24.155 12.116,16.884 17.3,11.7 v1(17.3,8.15)
  Bottom Layer w0.2: v1(12.217,24.257) 14.641,24.257 16.134,25.75 U1.125@17.525,25.75 ; v1(17.3,8.15) HDR2.7@17.3,9.7
IO1: HDR2.9 U1.126 | length 28.1
  Top Layer w0.2: v1(12.7,25.248) 12.979,24.968 12.979,23.927 12.522,23.47 12.522,17.043 18.1,11.466 v1(18.1,7.375)
  Bottom Layer w0.2: v1(12.7,25.248) 15.066,25.248 16.069,26.25 U1.126@17.525,26.25 ; v1(18.1,7.375) HDR2.9@18.1,9.7
IO2: HDR2.11 U1.127 | length 26.8
  Top Layer w0.2: v1(13.284,26.187) 13.462,26.01 13.462,23.825 12.932,23.296 12.932,17.211 18.9,11.243 v1(18.9,8.15)
  Bottom Layer w0.2: v1(13.284,26.187) 15.44,26.187 16.003,26.75 U1.127@17.525,26.75 ; v1(18.9,8.15) HDR2.11@18.9,9.7
IO3: HDR2.13 U1.128 | length 30.9
  Top Layer w0.2: v1(12.725,27.254) 13.31,27.254 14.046,26.518 14.046,23.844 13.335,23.133 13.335,17.374 19.7,11.009 v1@19.7,7.3
  Bottom Layer w0.2: v1(12.725,27.254) 17.521,27.254 U1.128@17.525,27.25 ; v1(19.7,7.375) HDR2.13@19.7,9.7
IO4: HDR2.15 U1.131 | length 29.4
  Top Layer w0.2: v1(13.462,28.092) 14.453,27.102 14.453,23.673 13.741,22.962 13.741,17.551 20.5,10.793 v1(20.5,8.15)
  Bottom Layer w0.2: v1(13.462,28.092) 14.402,28.092 15.059,28.75 U1.131@17.525,28.75 ; v1@20.5,8.175 v1(20.5,8.15) HDR2.15@20.5,9.7
IO5: HDR2.17 U1.132 | length 30.9
  Top Layer w0.2: v1(14.173,28.981) 14.859,28.296 14.859,23.514 14.148,22.802 14.148,17.755 21.311,10.592 v1(21.3,7.375)
  Bottom Layer w0.2: v1(14.173,28.981) 14.442,29.25 U1.132@17.525,29.25 ; v1(21.3,7.375) HDR2.17@21.3,9.7
IO6: HDR2.19 U1.133 | length 40.9
  Bottom Layer w0.2: U1.133@17.525,29.75 13.163,29.75 11.45,28.037 11.45,23.774 13.25,21.974 13.25,11.509 12.4,10.659 12.4,8.441 13.398,7.442 16.328,7.442 17.17,6.6 21.8,6.6 22.1,6.9 HDR2.19@22.1,9.7
IO7: HDR2.21 U1.134 | length 43.5
  Bottom Layer w0.2: U1.134@17.525,30.25 13.097,30.25 11.05,28.203 11.05,23.609 12.85,21.809 12.85,11.675 12,10.825 12,8.275 13.233,7.042 16.148,7.042 16.99,6.2 22.659,6.2 22.9,6.441 HDR2.21@22.9,9.7
IO8: HDR2.23 U1.135 | length 45.8
  Bottom Layer w0.2: U1.135@17.525,30.75 13.031,30.75 10.65,28.369 10.65,23.443 12.45,21.643 12.45,11.84 11.6,10.99 11.6,8.106 13.064,6.642 15.964,6.642 16.806,5.8 22.985,5.8 23.7,6.515 HDR2.23@23.7,9.7
IO9: HDR2.25 U1.136 | length 48
  Bottom Layer w0.2: U1.136@17.525,31.25 12.966,31.25 10.25,28.534 10.25,23.277 12.05,21.477 12.05,12.006 11.2,11.156 11.2,7.941 12.898,6.242 15.78,6.242 16.622,5.4 23.15,5.4 24.5,6.75 HDR2.25@24.5,9.7
IO10: HDR2.27 U1.137 | length 50.1
  Bottom Layer w0.2: U1.137@17.525,31.75 12.9,31.75 9.85,28.7 9.85,23.112 11.65,21.312 11.65,12.172 10.8,11.322 10.8,7.775 12.733,5.842 15.57,5.842 16.412,5 23.316,5 25.3,6.984 HDR2.27@25.3,9.7
IO11: HDR2.29 U1.138 | length 58.2
  Bottom Layer w0.2: U1.138@17.525,32.25 12.794,32.25 9.449,28.905 9.449,21.157 4.7,16.408 4.7,8.814 8.072,5.442 15.386,5.442 16.228,4.6 23.482,4.6 26.1,7.218 HDR2.29@26.1,9.7
IO12: HDR2.31 U1.139 | length 60.5
  Bottom Layer w0.2: U1.139@17.525,32.75 12.684,32.75 9.042,29.108 9.042,21.316 4.3,16.574 4.3,8.629 7.886,5.042 15.202,5.042 16.044,4.2 23.647,4.2 26.9,7.453 HDR2.31@26.9,9.7
IO13: HDR2.33 U1.140 | length 62.7
  Bottom Layer w0.2: U1.140@17.525,33.25 12.6,33.25 8.636,29.286 8.636,21.476 3.9,16.74 3.9,8.444 7.702,4.642 15.017,4.642 15.86,3.8 23.813,3.8 27.7,7.687 HDR2.33@27.7,9.7
IO14: HDR2.35 U1.141 | length 64.9
  Bottom Layer w0.2: U1.141@17.525,33.75 12.516,33.75 8.23,29.464 8.23,21.635 3.5,16.905 3.5,8.26 7.518,4.242 14.852,4.242 15.694,3.4 23.979,3.4 28.5,7.921 HDR2.35@28.5,9.7
IO15: HDR2.37 U1.143 | length 67.3
  Bottom Layer w0.2: U1.143@17.525,34.75 16.775,34.75 16.175,34.15 12.331,34.15 7.823,29.642 7.823,21.794 3.1,17.071 3.1,8.076 7.334,3.842 14.675,3.842 15.517,3 24.144,3 29.3,8.156 HDR2.37@29.3,9.7
IO16: HDR2.39 U1.144 | length 69.5
  Bottom Layer w0.2: U1.144@17.525,35.25 16.466,35.25 15.766,34.55 12.147,34.55 7.417,29.82 7.417,21.954 2.7,17.237 2.7,7.892 7.163,3.429 14.522,3.429 15.351,2.6 24.31,2.6 30.1,8.39 HDR2.39@30.1,9.7
IO17: HDR2.41 U1.156 | length 76.5
  Bottom Layer w0.2: U1.156@17.525,41.25 14.224,41.25 10.516,37.541 10.516,33.484 7.01,29.979 7.01,22.113 2.3,17.403 2.3,7.708 6.979,3.029 14.345,3.029 15.174,2.2 24.577,2.2 30.9,8.523 HDR2.41@30.9,9.7
IO18: HDR2.43 U1.158 | length 79
  Bottom Layer w0.2: U1.158@17.525,42.25 14.64,42.25 10.109,37.719 10.109,33.643 6.604,30.138 6.604,22.272 1.9,17.568 1.9,7.523 6.807,2.616 14.192,2.616 15.008,1.8 24.99,1.8 31.7,8.51 HDR2.43@31.7,9.7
